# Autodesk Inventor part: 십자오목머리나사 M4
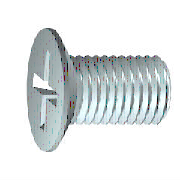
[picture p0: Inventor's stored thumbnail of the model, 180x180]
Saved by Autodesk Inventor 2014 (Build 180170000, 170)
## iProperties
IsCustomPart: 0
Created: 2012-02
Part Number: 십자오목머리나사 M4
Material: 강철, 연강
Description: 십자 오목 머리 나사
Document SubType Name: Modeling
Standard: KS B 1023
Designer: mduedu
Standards Organization: KS
Language: ko-KR
Size Designation: A  M 4 x 12 - H
Categories: <MemberInstance><Categories><Category DisplayName="조임쇠" InternalName="e4da775c-781d-43d5-af7c-5136215cf5a6" Mnemonic="FSTN"><Category DisplayName="볼트" InternalN
Density: 7.86 g/cm^3
Mass: 1.50482 g
Surface Area: 2.78557 cm^2
Volume: 0.191453 cm^3
Appearance: 주황색
Author: mduedu
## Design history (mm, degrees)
body "Solid1"
sketch "스케치1"
  geometry: L1 (2.6, 0)-(12, 0); L2 (12, 0)-(12, 2); L3 (12, 2)-(4.1, 2); L4 (4.1, 2)-(3.671, 1.785); L5 (3.671, 1.785)-(2.7, 1.785); L6 (0, 4.2)-(0, 2.4); L7 (0, 2.4)-(1.801, 1.502); L8 (1.801, 1.502)-(2.6, 0); L9 (-2.4, 0)-(14.4, 0) reference; L10 (0, -0.84)-(0, 5.04) reference; L11 (0, 4.2)-(0.285, 4.2); L12 (0.285, 4.2)-(2.7, 1.785); L13 (4.1, 2)-(2.485, 2)
  constraints: 22 end point, 3 parallel, 3 perpendicular, 2 collinear, 1 horizontal, 1 point on line
  dimensions: "d1" = 7.9 distance of L2.end L3.end (= GEL); "d2" = 4 diameter of L3 L1 (= GD); "d3" = 3.57058 diameter of L5 L1 (= BDM); "d4" = 4.8 diameter of L6.end L1 (= SDM); "d5" = 26.5 deg angle of L7 L1; "d6" = 62 deg angle of L8 L1; "d7" = 2.6 distance from line of L1.start L6 (= INTI); "d8" = 0.42941 horizontal distance of L4.end L3.end (= GAL); "d12" = 8.4 diameter of L11 L1 (= KOD); "d13" = 45 deg angle of L12 L1 (= 0.5 x SEWI); "d15" = 12 distance between parallel lines of L2 L6 (= NLG); "d24" = 2.7 distance from line of L5.end L6 (= KOH)
revolve "본체" stored, may be unused: angle "d16" = 90 deg
sketch "스케치2"
  geometry: L1 (0, 2.4)-(0, 0); L2 (0, 0)-(2.4, 0); L3 (0, 0)-(1.697, 1.697); L4 (0.312, 2.38)-(0.408, 0.734); L5 (2.38, 0.312)-(0.734, 0.408); L6 (0, -5.88)-(0, 5.88) reference; L7 (-5.88, 0)-(5.88, 0) reference; L8 (2.38, -0.312)-(0.734, -0.408); L9 (0.312, -2.38)-(0.408, -0.734); L10 (-0.312, -2.38)-(-0.408, -0.734); L11 (-2.38, -0.312)-(-0.734, -0.408); L12 (-2.38, 0.312)-(-0.734, 0.408); L13 (-0.312, 2.38)-(-0.408, 0.734); A1 r 0.72 centre (0, 0) between (0.72, 0) and (0, 0.72); A2 r 0.84 centre (0, 0) between (0.84, 0) and (0, 0.84); A3 r 2.4 centre (0, 0) between (2.38, 0.312) and (0.312, 2.38); A4 r 2.4 centre (0, 0) between (0.312, 2.38) and (0, 2.4); A5 r 2.4 centre (0, 0) between (2.4, 0) and (2.38, 0.312); A6 r 2.4 centre (0, 0) between (0, -2.4) and (0.312, -2.38); A7 r 2.4 centre (0, 0) between (0.312, -2.38) and (2.38, -0.312); A8 r 2.4 centre (0, 0) between (2.38, -0.312) and (2.4, 0); A9 r 2.4 centre (0, 0) between (0, 2.4) and (-0.312, 2.38); A10 r 2.4 centre (0, 0) between (-0.312, 2.38) and (-2.38, 0.312); A11 r 2.4 centre (0, 0) between (-2.38, 0.312) and (-2.4, 0); A12 r 2.4 centre (0, 0) between (-2.4, 0) and (-2.38, -0.312); A13 r 2.4 centre (0, 0) between (-2.38, -0.312) and (-0.312, -2.38); A14 r 2.4 centre (0, 0) between (-0.312, -2.38) and (0, -2.4); A15 r 0.347 centre (0.755, 0.755) between (0.408, 0.734) and (0.734, 0.408); A16 r 0.347 centre (0.755, -0.755) between (0.734, -0.408) and (0.408, -0.734); A17 r 0.347 centre (-0.755, -0.755) between (-0.408, -0.734) and (-0.734, -0.408); A18 r 0.347 centre (-0.755, 0.755) between (-0.734, 0.408) and (-0.408, 0.734); 3 further points
  constraints: 41 point on circle, 22 end point, 22 symmetric about line, 18 centre point, 11 coincident, 4 point on line, 3 tangent, 2 collinear, 1 perpendicular, 1 vertical, 19 other
  dimensions: "d17" = 1.44 diameter of A1 (= 0.3 x SDM); "d18" = 1.68 diameter of A2 (= 0.35 x SDM); "d19" = 4.8 diameter of A3 (= SDM); "d20" = 45 deg angle of L3 L2; "d21" = 0.3115 distance from line of L4.start L1 (= 0.5 x SBR)
extrude "슬롯" join sketch "스케치2" taper "d22" = 5 deg; stored distance "d79" = 25.4
fillet "모깎기1" dims "d23" = 0.1246 (= 0.2 x SBR)
feature "스레드" dims "d10" = 7.9 (= GEL), "d11" = 0
chamfer "모따기1" distance "d25" = 0.42941 (= -0.5 x SPD + 0.5 x GD); stored, may be unused: second distance "d26" = 0.21471 (= 0.5 x GAL), angle "d88" = 45 deg
workplane "Work Plane2"
other parameters: "NLG" = 12 [user parameter; used in 1 equation term], "GEL" = 7.9 [user parameter; used in 2 equation terms], "GAL" = 0.42941 (= 0.61345 x PTC) [user parameter; used in 3 equation terms], "SPD" = 3.14117 (= NND - 1.2269 x PTC) [user parameter; used in 1 equation term], "KOD" = 8.4 [user parameter; used in 1 equation term], "KOH" = 2.7 [user parameter; used in 1 equation term], "SBR" = 0.623 [user parameter; used in 2 equation terms], "INTI" = 2.6 [user parameter; used in 1 equation term], "SDM" = 4.8 [user parameter; used in 5 equation terms], "GD" = 4 (= NND) [user parameter; used in 2 equation terms], "BDM" = 3.57058 (= NND - GAL) [user parameter; used in 1 equation term], "SEWI" = 90 deg [user parameter; used in 1 equation term], "d9" = 4.8 (= SDM), "d27" = 0, "d91" = 0, "d92" = 0, "GUL" = 0.42941 (= 0.61345 x PTC) [user parameter], "TOA" = 30 deg [user parameter], "EPV" = 4.7 [user parameter], "THREADDIA" = 4 [user parameter; used in 1 equation term], "TPU" = 14.28571 (computed from PTC) [user parameter], "PTC" = 0.7 [user parameter; used in 5 equation terms], "NND" = 4 [user parameter; used in 3 equation terms], "GD1" = 3.14117 (= THREADDIA - 1.2269 x PTC) [user parameter]
